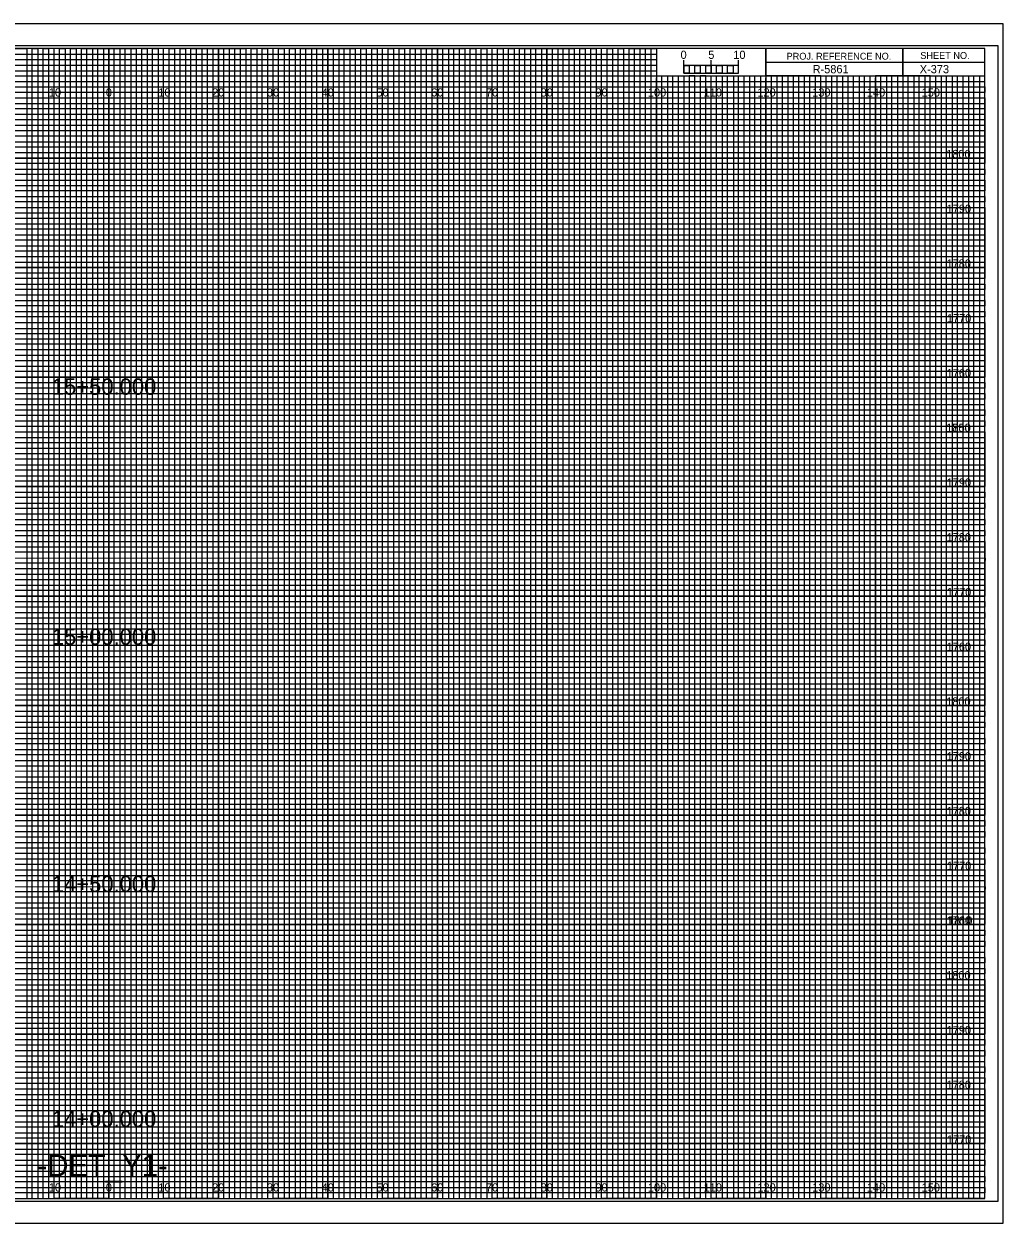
# Model space of a CAD drawing. Extents: x -13 to 323, y -5 to 874.
# Drawn here: x 144.5 to 323.3, y 435.5 to 654.5 of the extents above; entities that cross this region are included whole.
import ezdxf

# ---------------------------------------------------------------- set-up
doc = ezdxf.new("R2010")
doc.units = 0
for name, color, linetype in [('Prop Horizontal Alignment', 7, 'Continuous'), ('Prop XS Alignment Label', 7, 'Continuous'), ('Prop XS Bar Scale Labels', 7, 'Continuous'), ('Prop XS Earthwork Shape', 7, 'Continuous'), ('Prop XS Project Number', 7, 'Continuous'), ('Prop XS Sheet Number', 7, 'Continuous'), ('Raster_Level_0', 7, 'Continuous'), ('Scratch_Level_1', 7, 'Continuous'), ('Scratch_Level_3', 7, 'Continuous'), ('Sheet Cross Section CELL', 7, 'Continuous'), ('Sheet Cross Section Grid Minor 1 CELL', 7, 'Continuous'), ('Sheet Cross Section Grid Minor 2 CELL', 7, 'Continuous'), ('Sheet Cross Section Scale CELL', 7, 'Continuous'), ('Sheet Cutting Line CELL', 7, 'Continuous'), ('Sheet DOT Grid CELL', 7, 'Continuous'), ('Sheet Plot Border Inside CELL', 7, 'Continuous'), ('Sheet Plot Border Outside CELL', 7, 'Continuous')]:
    doc.layers.add(name, color=color, linetype=linetype)

msp = doc.modelspace()

# ---------------------------------------------------------------- linework, layer by layer
at = {"layer": 'Prop XS Earthwork Shape'}
for points in [[(135, 650), (145, 650), (145, 440), (155, 440), (155, 650), (165, 650), (165, 440), (175, 440), (175, 650), (185, 650), (185, 440), (195, 440), (195, 650), (205, 650), (205, 440), (215, 440), (215, 650), (225, 650), (225, 440), (235, 440), (235, 650), (245, 650), (245, 440), (255, 440), (255, 650), (259.93, 650), (260, 650), (260, 645), (264.99, 645), (264.99, 440), (275, 440), (275, 645), (285, 645), (285, 440), (295, 440), (295, 645), (305, 645), (305, 440), (315, 440), (315, 645)], [(0, 645), (275, 645)], [(0, 625), (320, 625), (320, 635), (0, 635)], [(0, 605), (320, 605), (320, 615), (0, 615)], [(0, 585), (320, 585), (320, 595), (0, 595)], [(0, 565), (320, 565), (320, 575), (0, 575)], [(0, 545), (320, 545), (320, 555), (0, 555)], [(0, 525), (320, 525), (320, 535), (0, 535)], [(0, 505), (320, 505), (320, 515), (0, 515)], [(0, 485), (320, 485), (320, 495), (0, 495)], [(0, 465), (320, 465), (320, 475), (0, 475)], [(0, 445), (320, 445), (320, 455), (0, 455)]]:
    msp.add_lwpolyline(points, dxfattribs=at)
at = {"layer": 'Scratch_Level_1'}
for p, q in [((150, 650), (140, 650)), ((150, 440), (150, 650)), ((170, 650), (160, 650)), ((160, 650), (160, 440)), ((170, 440), (170, 650)), ((190, 650), (180, 650)), ((180, 650), (180, 440)), ((190, 440), (190, 650)), ((210, 650), (200, 650)), ((200, 650), (200, 440)), ((210, 440), (210, 650)), ((230, 650), (220, 650)), ((220, 650), (220, 440)), ((230, 440), (230, 650)), ((250, 650), (240, 650)), ((240, 650), (240, 440)), ((250, 440), (250, 650)), ((260, 650), (260, 440)), ((270, 440), (270, 645)), ((290, 645), (280, 645)), ((280, 645), (280, 440)), ((290, 440), (290, 645)), ((310, 645), (300, 645)), ((300, 645), (300, 440)), ((310, 440), (310, 645)), ((160, 440), (150, 440)), ((180, 440), (170, 440)), ((200, 440), (190, 440)), ((220, 440), (210, 440)), ((240, 440), (230, 440)), ((260, 440), (250, 440)), ((280, 440), (270, 440)), ((300, 440), (290, 440)), ((320, 440), (310, 440)), ((320, 440), (320, 440))]:
    msp.add_line(p, q, dxfattribs=at)
for points in [[(0, 640), (320, 640), (320, 630), (0, 630)], [(0, 620), (320, 620), (320, 610), (0, 610)], [(0, 600), (320, 600), (320, 590), (0, 590)], [(0, 580), (320, 580), (320, 570), (0, 570)], [(0, 560), (320, 560), (320, 550), (0, 550)], [(0, 540), (320, 540), (320, 530), (0, 530)], [(0, 520), (320, 520), (320, 510), (0, 510)], [(0, 500), (320, 500), (320, 490), (0, 490)], [(0, 480), (320, 480), (320, 470), (0, 470)], [(0, 460), (320, 460), (320, 450), (0, 450)]]:
    msp.add_lwpolyline(points, dxfattribs=at)
at = {"layer": 'Sheet Cross Section CELL'}
for p, q in [((305, 650), (305, 645)), ((305, 645), (305, 650)), ((280, 647.5), (280, 645)), ((320, 647.49), (280, 647.49)), ((280, 645), (320, 645))]:
    msp.add_line(p, q, dxfattribs=at)
for points in [[(320, 650), (0, 650), (0, 440), (320, 440)], [(280, 650), (260, 650), (260, 645.03), (280, 645.03)], [(320, 650), (280, 650), (280, 645), (320, 645)]]:
    msp.add_lwpolyline(points, close=True, dxfattribs=at)
at = {"layer": 'Sheet Cross Section Grid Minor 1 CELL'}
for p, q in [((0, 649), (260, 649)), ((260, 649), (260, 647.98)), ((260, 647.98), (0, 647.98)), ((0, 647), (260, 647)), ((260, 647), (260, 645.89)), ((260, 645.89), (0, 645.89)), ((0, 644), (320, 644))]:
    msp.add_line(p, q, dxfattribs=at)
for points in [[(0, 643), (270, 643), (320, 643), (320, 642), (0, 642)], [(0, 641), (320, 641), (320, 639), (0, 639)], [(0, 638), (320, 638), (320, 637), (0, 636.98)], [(0, 636), (320, 636), (320, 634), (0, 634)], [(0, 633), (320, 633), (320, 632), (0, 632)], [(0, 631), (320, 631), (320, 629), (0, 629)], [(0, 628), (320, 628), (320, 627), (0, 627)], [(0, 626), (320, 626), (320, 624), (0, 624)], [(0, 623), (320, 623), (320, 622), (0, 622)], [(0, 621), (320, 621), (320, 619), (0, 619)], [(0, 618), (320, 618), (320, 617), (0, 617)], [(0, 616), (320, 616), (320, 613.95), (320, 613), (320, 612), (0, 612)], [(0, 614), (320, 614), (320, 613), (0, 613)], [(0, 611), (320, 611), (320, 609), (0, 609.03)], [(0, 609.03), (320, 609), (320, 608), (0, 608)], [(0, 607), (320, 607), (320, 606), (0, 606)], [(0, 604), (320, 604), (320, 603), (0, 603)], [(0, 602), (320, 602), (320, 601), (0, 601)], [(-0.07, 598.89), (320, 598.89), (320, 597.88), (-0.07, 597.88)], [(0, 597), (320, 597), (320, 596), (0, 596)], [(0, 594), (320, 594), (320, 593), (0, 593)], [(0, 592), (320, 592), (320, 591), (0, 591)], [(0, 589), (320, 589), (320, 588), (0, 588)], [(0, 587), (320, 587), (320, 586), (0, 586)], [(0, 584), (320, 584), (320, 583), (0, 583)], [(0, 582), (320, 582), (320, 581), (0, 581)], [(0, 579), (320, 579), (319.99, 577.98), (0, 578)], [(0, 577), (320, 577), (320, 576), (0, 576)], [(0, 574), (320, 574), (320, 573), (0, 573)], [(0, 572), (320, 572), (320, 571), (0, 571)], [(0, 569), (320, 569), (320, 568), (0, 568)], [(0, 567), (320, 567), (320, 566), (0, 566)], [(0, 564), (320, 564), (320, 563), (0, 563)], [(0, 562), (320, 562), (320, 561), (0, 561)], [(0, 559), (320, 559), (320, 558), (0, 558)], [(0, 556.99), (320.07, 556.91), (320, 556), (0, 556)], [(0, 554), (320, 554), (320, 553), (0, 553)], [(0, 552), (320, 552), (320, 551), (0, 551)], [(0, 549), (320, 549), (320, 548), (0, 548)], [(0, 547), (320, 547), (320, 546), (0, 546)], [(0, 544), (320, 544), (320, 543), (0, 543)], [(0, 542), (320, 542), (320, 541), (0, 541)], [(0, 539), (320, 539), (320, 538), (0, 538)], [(0, 537), (320, 537), (320, 536), (0, 536)], [(0, 534), (320, 534), (320, 533), (0, 533)], [(0, 532), (320, 532), (320, 531), (0, 531)], [(0, 529), (320, 529), (320, 528), (0, 528)], [(0, 527), (320, 527), (320, 526), (0, 526)], [(0, 524), (320, 524), (320, 523), (0, 523)], [(0, 522), (320, 522), (320, 521), (0, 521)], [(0, 519), (320, 519), (319.99, 517.98), (0, 518)], [(0, 517), (320, 517), (320, 516), (0, 516)], [(0, 514), (320, 514), (320, 513), (0, 513)], [(0, 512), (320, 512), (320, 511), (0, 511)], [(0, 509), (320, 509), (320, 508), (0, 508)], [(0, 507), (320, 507), (320, 506), (0, 506)], [(0, 504), (320, 504), (320, 503), (0, 503)], [(0, 502), (320, 502), (320, 501), (0, 501)], [(0, 499), (320, 499), (320, 498), (0, 498)], [(0, 496.99), (320.07, 496.91), (320, 496), (0, 496)], [(0, 494), (320, 494), (320, 493), (0, 493)], [(0, 492), (320, 492), (320, 491), (0, 491)], [(0, 489), (320, 489), (320, 488), (0, 488)], [(0, 487), (320, 487), (320, 486), (0, 486)], [(0, 484), (320, 484), (320, 483), (0, 483)], [(0, 482), (320, 482), (320, 481), (0, 481)], [(0, 479), (320, 479), (320, 478), (0, 478)], [(0, 477), (320, 477), (320, 476), (0, 476)], [(0, 474), (320, 474), (320, 473), (0, 473)], [(0, 472), (320, 472), (320, 471), (0, 471)], [(0, 469), (320, 469), (320, 468), (0, 468)], [(0, 467), (320, 467), (320, 466), (0, 466)], [(0, 464), (320, 464), (320, 463), (0, 463)], [(0, 462), (320, 462), (320, 461), (0, 461)], [(0, 459), (320, 459), (320, 458), (0, 458)], [(0, 457), (320, 457), (320, 456), (0, 456)], [(0, 454), (320, 454), (320, 453), (0, 453)], [(0, 452), (320, 452), (320, 451), (0, 451)], [(0, 449), (320, 449), (320, 448), (0, 448)], [(0, 447), (320, 447), (320, 446), (0, 446)], [(0, 444), (320, 444), (320, 443), (0, 443)], [(0, 442), (320, 442), (320, 441), (0, 441)]]:
    msp.add_lwpolyline(points, dxfattribs=at)
at = {"layer": 'Sheet Cross Section Grid Minor 2 CELL'}
for p, q in [((267, 645), (266.01, 645)), ((266.01, 645), (266.01, 440)), ((267, 440), (267, 645)), ((269, 645), (268, 645)), ((268, 645), (268, 440)), ((269, 440), (269, 645)), ((266.01, 440), (265, 440)), ((268, 440), (267, 440))]:
    msp.add_line(p, q, dxfattribs=at)
for points in [[(145, 440), (146, 440), (146, 650), (147, 650), (147, 440)], [(147, 440), (148, 440), (148, 650), (149, 650), (149, 440)], [(150, 440), (151, 440), (151, 650), (152, 650), (152, 440)], [(152, 440), (153, 440), (153, 650), (154, 650), (154, 440)], [(155, 440), (156, 440), (156, 650), (157, 650), (157, 440)], [(157, 440), (158, 440), (158, 650), (159, 650), (159, 440)], [(160, 440), (161, 440), (161, 650), (162, 650), (162, 440)], [(162, 440), (163, 440), (163, 650), (164, 650), (164, 440)], [(165, 440), (166, 440), (166, 650), (167, 650), (167, 440)], [(167, 440), (168, 440), (168, 650), (169, 650), (169, 440)], [(170, 440), (171, 440), (171, 650), (172, 650), (172, 440)], [(172, 440), (173, 440), (173, 650), (174, 650), (174, 440)], [(175, 440), (176, 440), (176, 650), (177, 650), (177, 440)], [(177, 440), (178, 440), (178, 650), (179, 650), (179, 440)], [(180, 440), (181, 440), (181, 650), (182, 650), (182, 440)], [(182, 440), (183, 440), (183, 650), (184, 650), (184, 440)], [(185, 440), (186, 440), (186, 650), (187, 650), (187, 440)], [(187, 440), (188, 440), (188, 650), (189, 650), (189, 440)], [(190, 440), (191, 440), (191, 650), (192, 650), (192, 440)], [(192, 440), (193, 440), (193, 650), (194, 650), (194, 440)], [(195, 440), (196, 440), (196, 650), (197, 650), (197, 440)], [(197, 440), (198, 440), (198, 650), (199, 650), (199, 440)], [(200, 440), (201, 440), (201, 650), (202, 650), (202, 440)], [(202, 440), (203, 440), (203, 650), (204, 650), (204, 440)], [(205, 440), (206, 440), (206, 650), (207, 650), (207, 440)], [(207, 440), (208, 440), (208, 650), (209, 650), (209, 440)], [(210, 440), (211, 440), (211, 650), (212, 650), (212, 440)], [(212, 440), (213, 440), (213, 650), (214, 650), (214, 440)], [(215, 440), (216, 440), (216, 650), (217, 650), (217, 440)], [(217, 440), (218, 440), (218, 650), (219, 650), (219, 440)], [(220, 440), (221, 440), (221, 650), (222, 650), (222, 440)], [(222, 440), (223, 440), (223, 650), (224, 650), (224, 440)], [(225, 440), (226, 440), (226, 650), (227, 650), (227, 440)], [(227, 440), (228, 440), (228, 650), (229, 650), (229, 440)], [(230, 440), (231, 440), (231, 650), (232, 650), (232, 440)], [(232, 440), (233, 440), (233, 650), (234, 650), (234, 440)], [(235, 440), (236, 440), (236, 650), (237, 650), (237, 440)], [(237, 440), (238, 440), (238, 650), (239, 650), (239, 440)], [(240, 440), (241, 440), (241, 650), (242, 650), (242, 440)], [(242, 440), (243, 440), (243, 650), (244, 650), (244, 440)], [(245, 440), (246, 440), (246, 650), (247, 650), (247, 440)], [(247, 440), (248, 440), (248, 650), (249, 650), (249, 440)], [(250, 440), (251, 440), (251, 650), (252, 650), (252, 440)], [(252, 440), (253, 440), (253, 650), (254, 650), (254, 440)], [(255, 440), (256, 440), (256, 650), (257, 650), (257, 440)], [(257, 440), (258, 440), (258, 650), (259, 650), (259, 440)], [(260, 440), (261, 440), (261, 645), (262.02, 645), (262.02, 440)], [(262, 440), (263, 440), (263, 645), (263.99, 645), (263.99, 440)], [(270, 440), (270.98, 440), (270.98, 645), (272, 645), (272, 440)], [(272, 440), (273, 440), (273, 645), (274.05, 645), (274.05, 440)], [(275, 440), (276, 440), (276, 645), (277, 645), (277, 440)], [(277, 440), (278, 440), (278, 645), (279, 645), (279, 440)], [(280, 440), (281, 440), (281, 645), (282, 645), (282, 440)], [(282, 440), (283, 440), (283, 645), (284, 645), (284, 440)], [(285, 440), (286, 440), (286, 645), (287, 645), (287, 440)], [(287, 440), (288, 440), (288, 645), (289, 645), (289, 440)], [(290, 440), (291, 440), (291, 645), (292, 645), (292, 440)], [(292, 440), (293, 440), (293, 645), (294, 645), (294, 440)], [(295, 440), (296, 440), (296, 645), (297, 645), (297, 440)], [(297, 440), (298, 440), (298, 645), (299, 645), (299, 440)], [(300, 440), (301, 440), (301, 645), (302, 645), (302, 440)], [(302, 440), (303, 440), (303, 645), (304, 645), (304, 440)], [(305, 440), (306, 440), (306, 645), (307, 645), (307, 440)], [(307, 440), (308, 440), (308, 645), (309, 645), (309, 440)], [(310, 440), (311, 440), (311, 645), (312, 645), (312, 440)], [(312, 440), (313, 440), (313, 645), (314, 645), (314, 440)], [(315, 440), (316, 440), (316, 645), (317, 645), (317, 440)], [(317, 440), (318, 440), (318, 645), (319, 645), (319, 440)]]:
    msp.add_lwpolyline(points, dxfattribs=at)
at = {"layer": 'Sheet Cross Section Scale CELL'}
for p, q in [((265, 645.49), (265, 647.9)), ((265, 646.9), (265, 647.9)), ((270, 645.49), (270, 647.9)), ((275, 645.49), (275, 647.9)), ((275, 646.9), (275, 647.9))]:
    msp.add_line(p, q, dxfattribs=at)
for points in [[(275, 646.9), (265, 646.9), (265, 645.49), (275, 645.49)], [(265, 646.9), (266, 646.9), (266, 645.49), (265, 645.49)], [(267, 646.9), (268, 646.9), (268, 645.49), (267, 645.49)], [(269, 646.9), (270, 646.9), (270, 645.49), (269, 645.49)], [(271, 646.9), (272, 646.9), (272, 645.49), (271, 645.49)], [(273, 646.9), (274, 646.9), (274, 645.49), (273, 645.49)]]:
    msp.add_lwpolyline(points, close=True, dxfattribs=at)
at = {"layer": 'Sheet Cutting Line CELL'}
for p, q in [((323.3, 654.5), (-13.4, 654.5)), ((-13.4, 435.5), (323.3, 435.5))]:
    msp.add_line(p, q, dxfattribs=at)
at = {"layer": 'Sheet DOT Grid CELL'}
for p, q in [((150, 440), (150, 650)), ((160, 440), (160, 650)), ((170, 440), (170, 650)), ((180, 440), (180, 650)), ((190, 440), (190, 650)), ((200, 440), (200, 650)), ((210, 440), (210, 650)), ((220, 440), (220, 650)), ((230, 440), (230, 650)), ((240, 440), (240, 650)), ((250, 440), (250, 650)), ((260, 440), (260, 644.69)), ((270, 440), (270, 644.69)), ((280, 440), (280, 644.69)), ((290, 440), (290, 644.69)), ((300, 440), (300, 644.69)), ((310, 440), (310, 644.69)), ((0, 640), (320, 640)), ((0, 630), (320, 630)), ((0, 620), (320, 620)), ((0, 610), (320, 610)), ((0, 600), (320, 600)), ((0, 590), (320, 590)), ((0, 580), (320, 580)), ((0, 570), (320, 570)), ((0, 560), (320, 560)), ((0, 550), (320, 550)), ((0, 540), (320, 540)), ((0, 530), (320, 530)), ((0, 520), (320, 520)), ((0, 510), (320, 510)), ((0, 500), (320, 500)), ((0, 490), (320, 490)), ((0, 480), (320, 480)), ((0, 470), (320, 470)), ((0, 460), (320, 460)), ((0, 450), (320, 450))]:
    msp.add_line(p, q, dxfattribs=at)
at = {"layer": 'Sheet Plot Border Inside CELL'}
msp.add_lwpolyline([(-10.8, 439.5), (322.4, 439.5), (322.4, 650.5), (-10.8, 650.5)], close=True, dxfattribs=at)
at = {"layer": 'Sheet Plot Border Outside CELL'}
msp.add_lwpolyline([(-13.4, 435.5), (323.3, 435.5), (323.3, 654.5), (-13.4, 654.5)], close=True, dxfattribs=at)

# ---------------------------------------------------------------- texts
at = {"layer": 'Prop Horizontal Alignment'}
for s, p in [('15+50.000', (149.59, 586.77)), ('15+00.000', (149.59, 541.09)), ('14+50.000', (149.59, 495.94)), ('14+00.000', (149.59, 453.02))]:
    msp.add_text(s, height=3, dxfattribs=at).set_placement(p)
at = {"layer": 'Prop XS Alignment Label'}
msp.add_text('-DET_Y1-', height=4, dxfattribs=at).set_placement((146.97, 444))
at = {"layer": 'Prop XS Bar Scale Labels'}
for s, p in [('5', (269.47, 648.12)), ('10', (274.04, 648.12))]:
    msp.add_text(s, height=1.5, dxfattribs=at).set_placement(p)
at = {"layer": 'Prop XS Project Number'}
msp.add_text('R-5861', height=1.5, dxfattribs=at).set_placement((288.53, 645.5))
at = {"layer": 'Prop XS Sheet Number'}
msp.add_text('X-373', height=1.5, dxfattribs=at).set_placement((308.09, 645.5))
at = {"layer": 'Raster_Level_0'}
for s, p in [('10', (149.04, 641.25)), ('0', (159.45, 641.25)), ('0', (159.45, 641.25)), ('10', (169.04, 641.25)), ('20', (178.86, 641.25)), ('30', (188.86, 641.25)), ('40', (198.86, 641.25)), ('50', (208.86, 641.25)), ('60', (218.86, 641.25)), ('70', (228.86, 641.25)), ('80', (238.86, 641.25)), ('90', (248.86, 641.25)), ('100', (258.44, 641.25)), ('110', (268.62, 641.25)), ('120', (278.44, 641.25)), ('130', (288.44, 641.25)), ('140', (298.44, 641.25)), ('150', (308.44, 641.25)), ('10', (149.04, 441.25)), ('0', (159.45, 441.25)), ('0', (159.45, 441.25)), ('10', (169.04, 441.25)), ('20', (178.86, 441.25)), ('30', (188.86, 441.25)), ('40', (198.86, 441.25)), ('50', (208.86, 441.25)), ('60', (218.86, 441.25)), ('70', (228.86, 441.25)), ('80', (238.86, 441.25)), ('90', (248.86, 441.25)), ('100', (258.44, 441.25)), ('110', (268.62, 441.25)), ('120', (278.44, 441.25)), ('130', (288.44, 441.25)), ('140', (298.44, 441.25)), ('150', (308.44, 441.25))]:
    msp.add_text(s, height=1.5, dxfattribs=at).set_placement(p)
at = {"layer": 'Scratch_Level_3'}
for s, p in [('1800', (312.92, 630)), ('1790', (313, 620)), ('1780', (312.98, 610)), ('1770', (313.04, 600)), ('1760', (313, 590)), ('1800', (312.92, 580)), ('1750', (312.96, 580)), ('1790', (313, 570)), ('1780', (312.98, 560)), ('1770', (313.04, 550)), ('1760', (313, 540)), ('1800', (312.92, 530)), ('1790', (313, 520)), ('1780', (312.98, 510)), ('1770', (313.04, 500)), ('1760', (313, 490)), ('1810', (313.25, 490)), ('1800', (312.92, 480)), ('1790', (313, 470)), ('1780', (312.98, 460)), ('1770', (313.04, 450))]:
    msp.add_text(s, height=1.5, dxfattribs=at).set_placement(p)
at = {"layer": 'Sheet Cross Section CELL'}
for s, p in [('PROJ. REFERENCE NO.', (283.77, 647.99)), ('SHEET NO.', (308.19, 648.12))]:
    msp.add_text(s, height=1.25, dxfattribs=at).set_placement(p)
at = {"layer": 'Sheet Cross Section Scale CELL'}
msp.add_text('0', height=1.5, dxfattribs=at).set_placement((264.41, 648.12))

doc.saveas('drawing.dxf')
